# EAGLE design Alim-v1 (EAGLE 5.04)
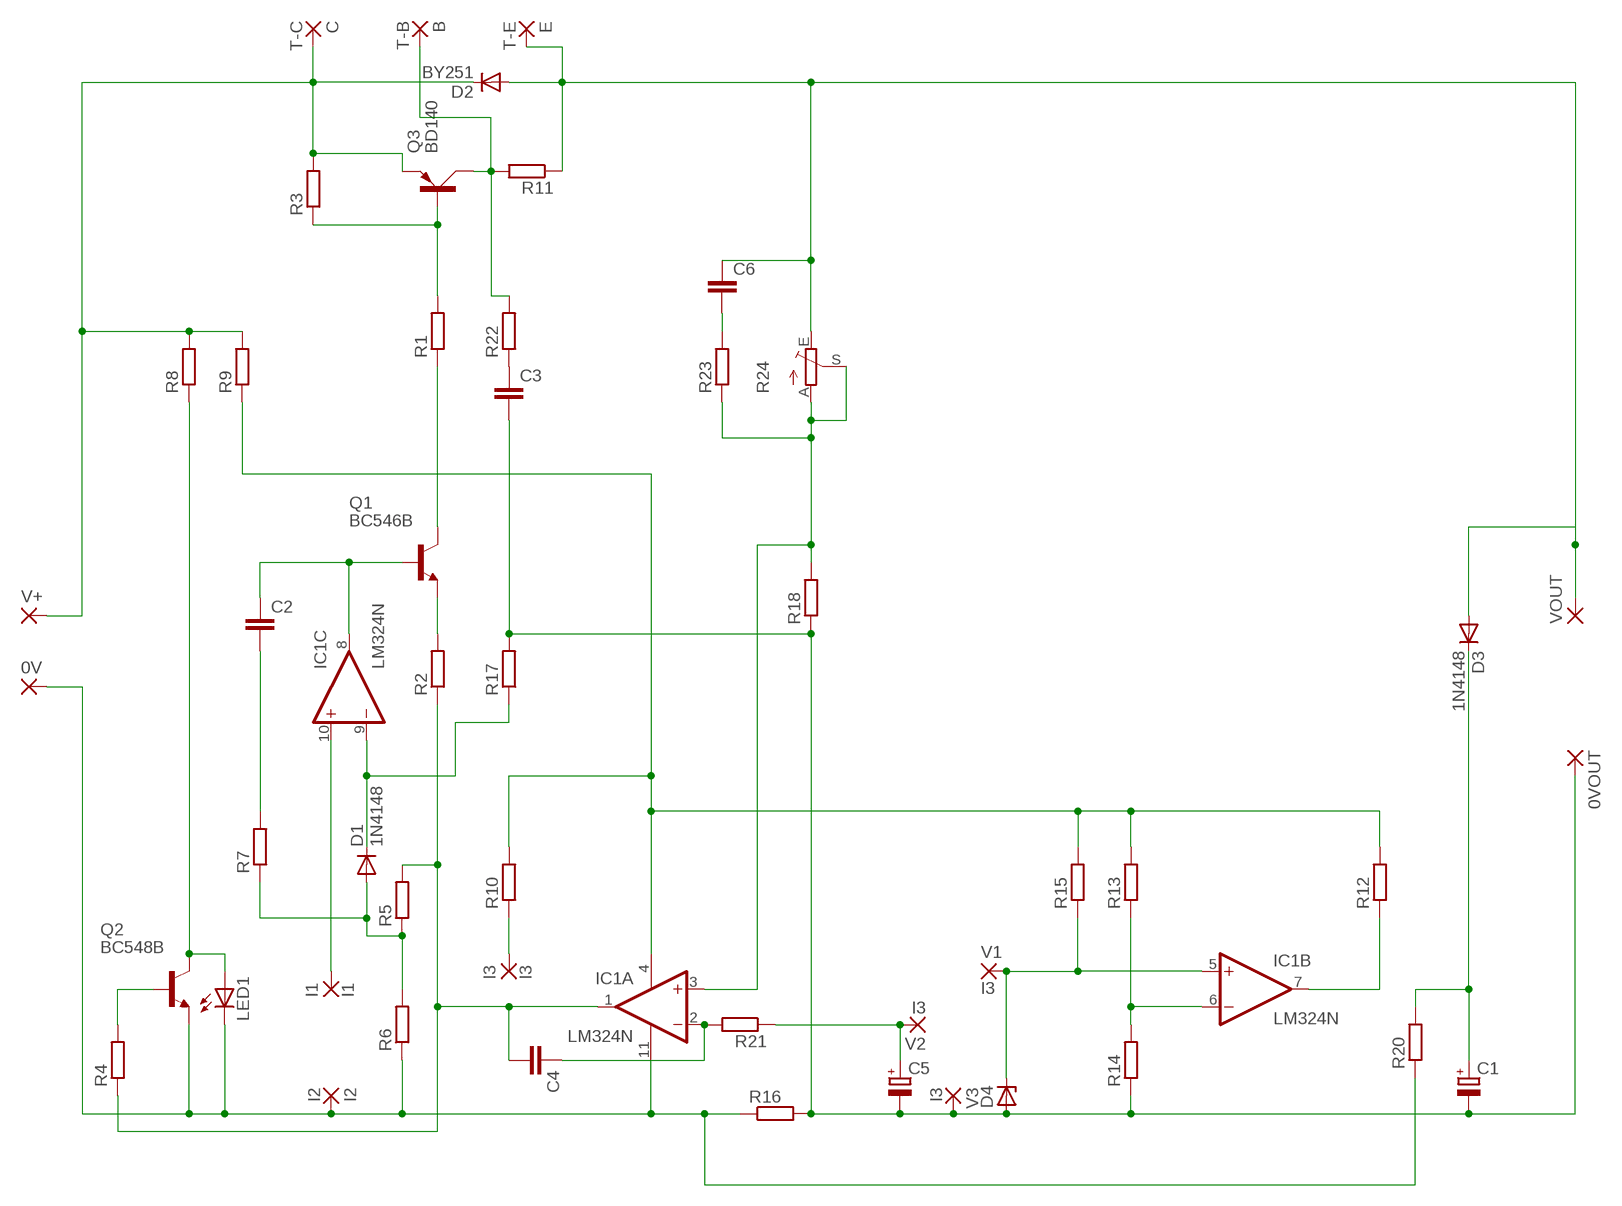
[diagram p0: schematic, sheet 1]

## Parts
0V  3,81/1,4  [3,81/1,4]
0VOUT  3,81/1,4  [3,81/1,4]
B  T-B  WIREPAD3,81/1,4  [3,81/1,4]
C  T-C  WIREPAD3,81/1,4  [3,81/1,4]
C1  CPOL-EUE2.5-5  [E2,5-5]
C2  C-EU025-025X050  [C025-025X050]
C3  C-EU025-025X050  [C025-025X050]
C4  C-EU025-025X050  [C025-025X050]
C5  CPOL-EUE2.5-5  [E2,5-5]
C6  C-EU025-025X050  [C025-025X050]
D1  1N4148  1N4148DO35-10  [DO35-10]
D2  BY251  [DO201-15]
D3  1N4148  1N4148DO35-10  [DO35-10]
D4  ZENER-DIODEDO41Z10  [DO41Z10]
E  T-E  WIREPAD3,81/1,4  [3,81/1,4]
I1  I1  WIREPAD1,6/0,9  [1,6/0,9]
I2  I2  WIREPAD1,6/0,9  [1,6/0,9]
I3  I3  WIREPAD1,6/0,9  [1,6/0,9]
IC1  LM324N  [DIL14]
LED1  LED5MM  [LED5MM]
Q1  BC546B  [TO92-EBC]
Q2  BC548B  [TO92-EBC]
Q3  BD140  [TO126AV]
R1  R-EU_0207/10  [0207/10]
R2  R-EU_0207/10  [0207/10]
R3  R-EU_0207/10  [0207/10]
R4  R-EU_0207/10  [0207/10]
R5  R-EU_0207/10  [0207/10]
R6  R-EU_0207/10  [0207/10]
R7  R-EU_0207/10  [0207/10]
R8  R-EU_0207/10  [0207/10]
R9  R-EU_0207/10  [0207/10]
R10  R-EU_0207/10  [0207/10]
R11  R-EU_0207/10  [0207/10]
R12  R-EU_0207/10  [0207/10]
R13  R-EU_0207/10  [0207/10]
R14  R-EU_0207/10  [0207/10]
R15  R-EU_0207/10  [0207/10]
R16  R-EU_0617/5V  [0617V]
R17  R-EU_0207/10  [0207/10]
R18  R-EU_0207/10  [0207/10]
R20  R-EU_0207/10  [0207/10]
R21  R-EU_0207/10  [0207/10]
R22  R-EU_0207/10  [0207/10]
R23  R-EU_0207/10  [0207/10]
R24  TRIM_EU-B64Y  [B64Y]
V1  I3  WIREPAD1,6/0,9  [1,6/0,9]
V2  I3  WIREPAD1,6/0,9  [1,6/0,9]
V3  I3  WIREPAD1,6/0,9  [1,6/0,9]
V+  3,81/1,4  [3,81/1,4]
VOUT  3,81/1,4  [3,81/1,4]

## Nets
N$1: Q3.B R1.2 R3.1
N$2: Q1.C R1.1
N$3: Q1.E R2.2
N$4: IC1.7(B:OUT) R12.1
N$5: Q2.B R4.2
N$6: C4.2 IC1.1(A:OUT) R2.1 R4.1 R5.2
N$7: D1.C IC1.9(C:-IN) R17.1
N$8: 0V.1(P) I2.1(P) IC1.11(P:V-) LED1.K(C) Q2.E R6.1 R16.1 R20.1
N$9: D1.A R5.1 R6.2 R7.1
N$10: LED1.A Q2.C R8.1
N$11: C.1(P) D2.C Q3.E R3.2 R8.2 R9.2 V+.1(P)
N$12: C2.1 IC1.8(C:OUT) Q1.B
N$13: I1.1(P) IC1.10(C:+IN)
N$14: I3.1(P) R10.1
N$15: IC1.4(P:V+) R9.1 R10.2 R12.2 R13.2 R15.2
N$16: 0VOUT.1(P) C1.- C3.2 C5.- D4.A R14.1 R16.2 R17.2 R18.1 V3.1(P)
N$17: B.1(P) Q3.C R11.2 R22.2
N$18: C6.1 D2.A D3.A E.1(P) R11.1 R24.E VOUT.1(P)
N$19: IC1.6(B:-IN) R13.1 R14.2
N$20: D4.C IC1.5(B:+IN) R15.1 V1.1(P)
N$21: IC1.3(A:+IN) R18.2 R23.1 R24.A R24.S
N$22: C4.1 IC1.2(A:-IN) R21.2
N$23: C2.2 R7.2
N$25: C1.+ D3.C R20.2
N$26: C3.1 R22.1
N$27: C5.+ R21.1 V2.1(P)
N$29: C6.2 R23.2
Unconnected: IC1.12(D:+IN) IC1.13(D:-IN) IC1.14(D:OUT)

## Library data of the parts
0V 0VOUT V+ VOUT = wirepad:3,81/1,4: THROUGH-HOLE PAD
B C E I1-I3 V1-V3 = wirepad:WIREPAD: Wire PAD connect wire on PCB
C1 C5 = rcl:CPOL-EU: POLARIZED CAPACITOR, European symbol
C2-C4 C6 = rcl:C-EU: CAPACITOR, European symbol
D1 D3 = diode:1N4148: DIODE
D2 = diode:BY251: DIODE
D4 = diode:ZENER-DIODE: Z-Diode
IC1 = linear:LM324: OP AMP
LED1 = led:LED: LED
Q1 = transistor-npn:BC546*: NPN Transistor
Q2 = transistor-npn:BC548*: NPN Transistor
Q3 = transistor-power:BD140: PNP TRANSISTOR
R1-R15 R17 R18 R20-R23 = resistor:R-EU_: RESISTOR, European symbol
R16 = rcl:R-EU_: RESISTOR, European symbol
R24 = pot:TRIM_EU-: POTENTIOMETER

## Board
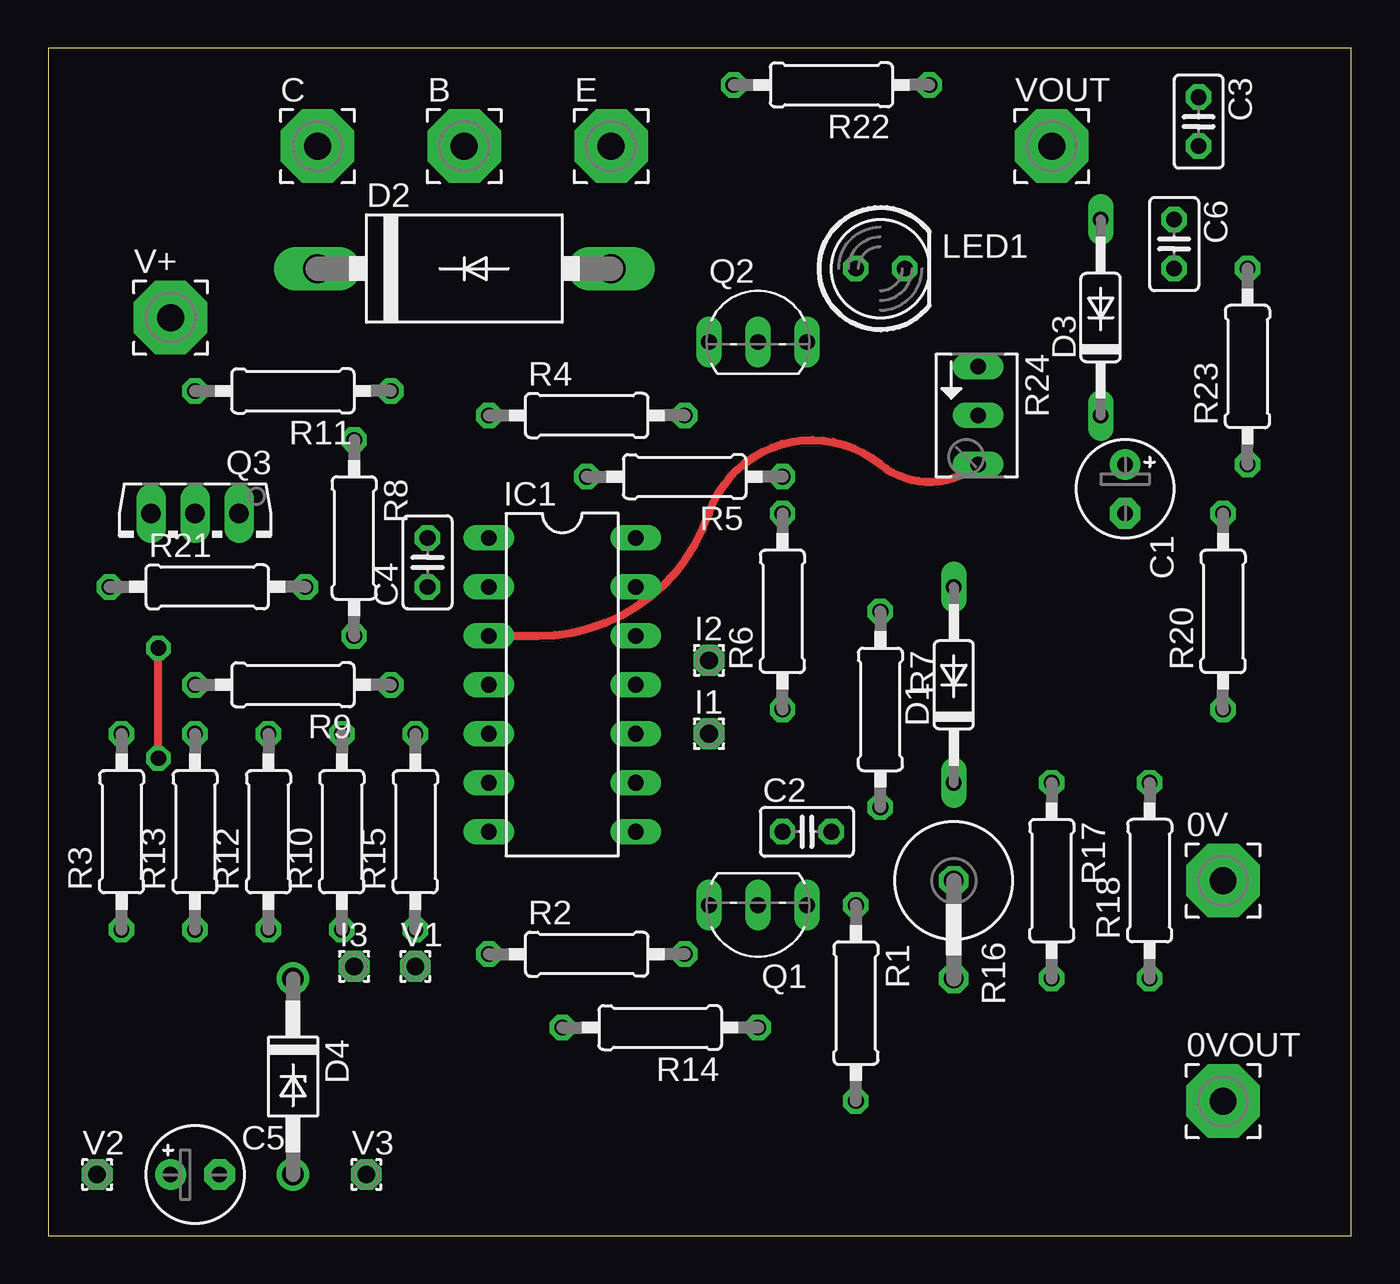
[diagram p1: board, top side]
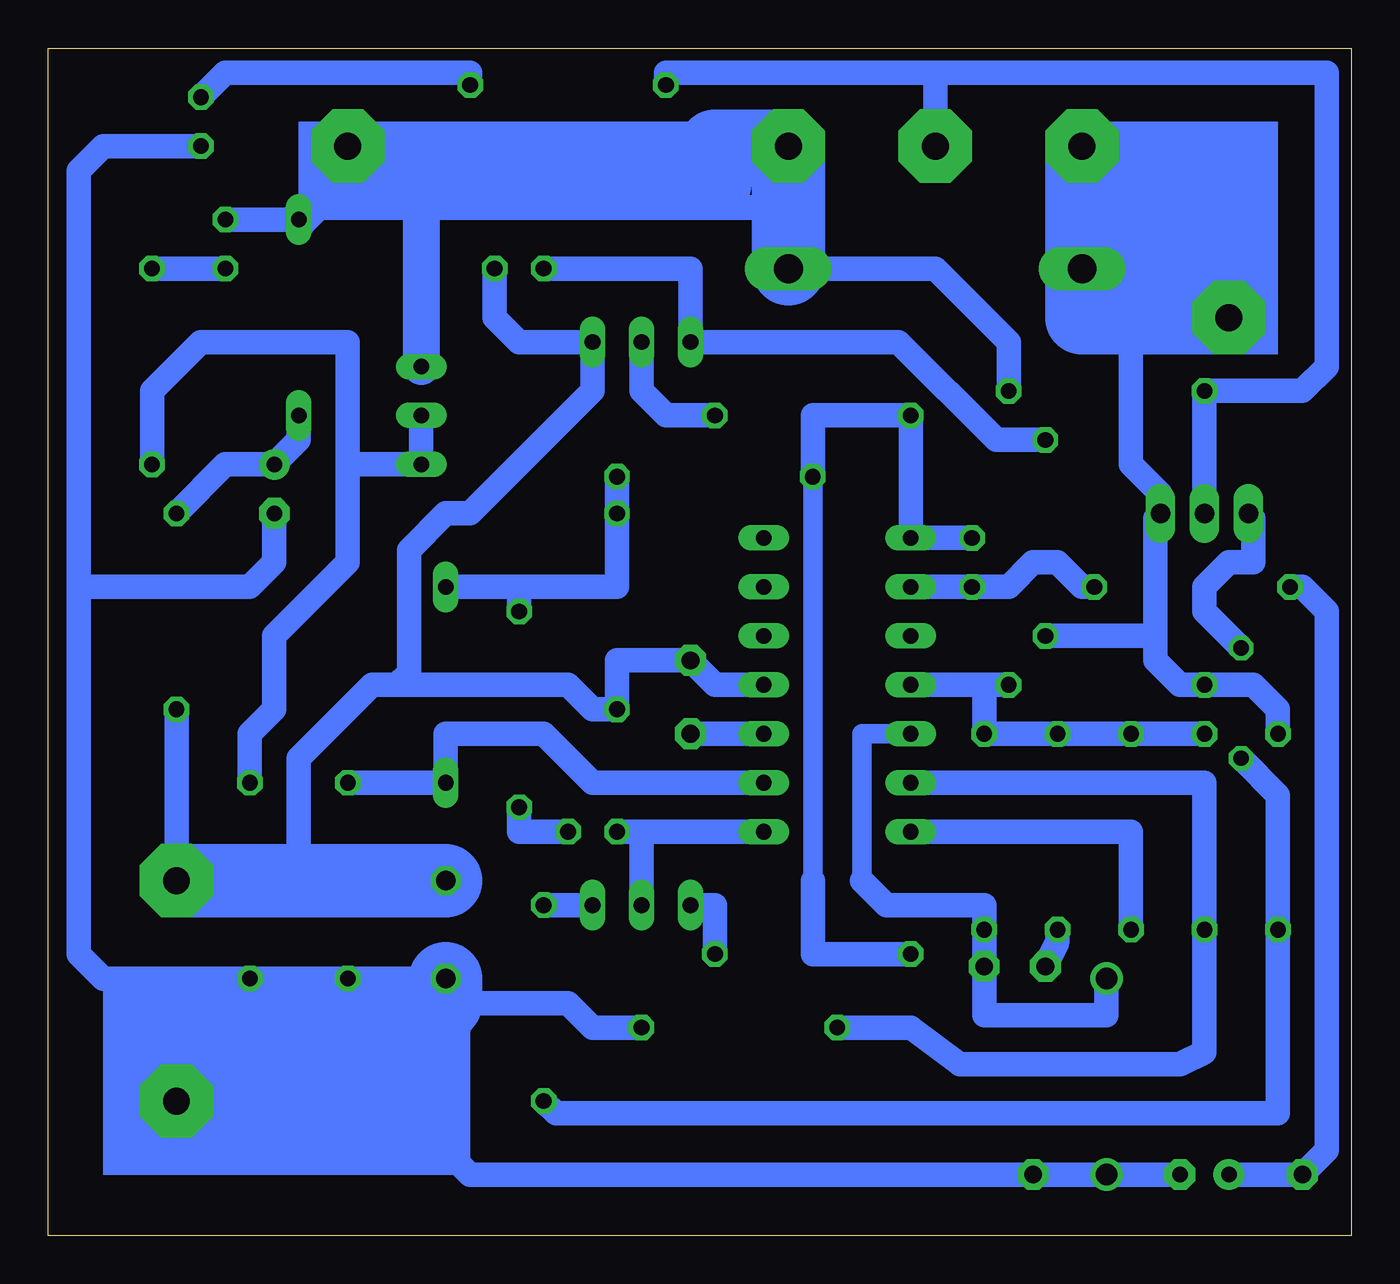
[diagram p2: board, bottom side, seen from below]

Size 67.61 x 61.59 mm. Coordinates in mm from the lower left corner, seen from the top.
Outline: 0,0 67.61,0 67.61,61.59 0,61.59 0,0
Copper layers (1*16): Top 0.035mm / dielectric 1.5mm / Bottom 0.035mm
Design rules "default": minimum track width 10mil, minimum drill 24mil, track to track 8mil, track to pad 8mil, pad to pad 8mil, via to via 8mil, smd to smd 8mil, copper to edge 40mil, drill to drill 8mil, minimum pad ring 10mil, minimum via ring 8mil, stop-mask expansion 4mil, vias tented up to drill 0mil, thermal gap 10mil

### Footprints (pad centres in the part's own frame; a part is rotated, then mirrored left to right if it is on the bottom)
3,81/1,4 = drill 1.397 pad 3.81 octagon: 1 0,0
E2,5-5 = drill 0.813 pad 1.6 round: + -1.27,0 | drill 0.813 pad 1.6 octagon: - 1.27,0
C025-025X050 = drill 0.813 octagon: 1 -1.27,0; 2 1.27,0
DO35-10 = drill 0.813 long: A 5.08,0; C -5.08,0
DO201-15 = drill 1.499 long: A 7.62,0; C -7.62,0
DO41Z10 = drill 1.118 round: A 5.08,0; C -5.08,0
1,6/0,9 = drill 0.914 pad 1.6 octagon: 1 0,0
DIL14 = drill 0.813 long: 1 -7.62,-3.81; 2 -5.08,-3.81; 3 -2.54,-3.81; 4 0,-3.81; 5 2.54,-3.81; 6 5.08,-3.81; 7 7.62,-3.81; 8 7.62,3.81; 9 5.08,3.81; 10 2.54,3.81; 11 0,3.81; 12 -2.54,3.81; 13 -5.08,3.81; 14 -7.62,3.81
LED5MM = drill 0.813 octagon: A -1.27,0; K 1.27,0
TO92-EBC = drill 0.813 long: B 0,-1.27; C -2.54,-1.27; E 2.54,-1.27
TO126AV = drill 1.016 long: B 2.286,-1.27; C 0,-1.27; E -2.286,-1.27
0207/10 = drill 0.813 octagon: 1 -5.08,0; 2 5.08,0
0617V = drill 1.016 octagon: 1 -2.54,0; 2 2.54,0
B64Y = drill 0.813 long: A 2.54,0; E -2.54,0; S 0,0

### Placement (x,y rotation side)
0V  60.96,18.41 0 top
0VOUT  60.96,6.98 0 top
B  21.59,56.52 0 top
C  13.97,56.52 0 top
C1  55.88,38.73 270 top
C2  39.37,20.95 0 top
C3  59.69,57.79 270 top
C4  19.68,34.93 90 top
C5  7.62,3.18 0 top
C6  58.42,51.43 270 top
D1  46.99,28.58 90 top
D2  21.59,50.16 0 top
D3  54.61,47.63 90 top
D4  12.7,8.26 270 top
E  29.21,56.52 0 top
I1  34.29,26.04 0 top
I2  34.29,29.84 0 top
I3  15.88,13.97 0 top
IC1  26.67,28.58 270 top
LED1  43.18,50.16 0 top
Q1  36.83,15.88 180 top
Q2  36.83,47.63 0 top
Q3  7.62,36.2 180 top
R1  41.91,12.07 270 top
R2  27.94,14.61 0 top
R3  3.81,20.95 90 top
R4  27.94,42.55 0 top
R5  33.02,39.37 180 top
R6  38.1,32.38 90 top
R7  43.18,27.3 270 top
R8  15.88,36.2 270 top
R9  12.7,28.58 180 top
R10  15.24,20.95 90 top
R11  12.7,43.81 180 top
R12  11.43,20.95 90 top
R13  7.62,20.95 90 top
R14  31.75,10.8 180 top
R15  19.05,20.95 90 top
R16  46.99,15.88 270 top
R17  52.07,18.41 270 top
R18  57.15,18.41 90 top
R20  60.96,32.38 90 top
R21  8.26,33.66 0 top
R22  40.64,59.69 180 top
R23  62.23,45.09 90 top
R24  48.26,42.55 270 top
V1  19.05,13.97 0 top
V2  2.54,3.18 0 top
V3  16.51,3.18 0 top
V+  6.35,47.63 0 top
VOUT  52.07,56.52 0 top

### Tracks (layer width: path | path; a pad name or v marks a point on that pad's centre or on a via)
N$1  (via drill 0.8 pad 1.27)
  Top 0.406: v5.71,24.77 v5.71,30.48
  Bottom 1.27: 3.81,14.61 3.81,6.35 41.28,6.35 R1.2 | 3.81,14.61 R3.1 | v5.71,30.48 7.62,32.38 7.62,33.66 6.35,34.93 5.08,34.93 5.08,37.21 Q3.B | 3.81,14.61 3.81,22.86 v5.71,24.77
N$2
  Bottom 1.27: Q1.C R1.1
N$3
  Bottom 1.27: R2.2 33.02,17.15 Q1.E
N$4
  Bottom 1.27: R12.1 11.43,20.95 IC1.7
N$5
  Bottom 1.27: R4.2 35.56,42.55 36.83,43.81 Q2.B
N$6
  Bottom 1.016: 27.94,18.41 R5.2
  Bottom 1.27: R2.1 27.94,14.61 27.94,18.41 | R5.2 27.94,42.55 R4.1 IC1.1 C4.2
N$7
  Bottom 1.27: IC1.9 39.37,23.49 41.91,26.04 46.99,26.04 D1.C R17.1
N$8
  Bottom 1.27: LED1.K 44.45,47.63 43.18,46.35 Q2.E 39.37,43.81 45.72,37.47 46.99,37.47 48.9,35.56 48.9,29.21 49.53,28.58 | 0V.1 R20.1 | IC1.11 33.02,28.58 I2.1 38.1,29.84 R6.1 39.37,27.3 40.64,28.58 49.53,28.58 | 49.53,28.58 50.8,28.58 54.61,24.77 54.61,18.41
  Bottom 3.81: R16.1 54.61,18.41 0V.1
N$9
  Bottom 1.27: R5.1 R6.2 38.1,33.66 43.18,33.66 | R7.1 43.18,33.66 | 43.18,33.66 D1.A
N$10
  Bottom 1.27: LED1.A 34.29,50.16 Q2.C 23.5,46.35 18.41,41.27 R8.1
N$11
  Bottom 1.27: 11.43,47.63 11.43,40.01 9.91,38.48 Q3.E 10.16,37.21 10.16,31.12 | R3.2 3.81,27.3 5.08,28.58 R9.2 8.89,28.58 10.16,29.84 10.16,31.12 | 10.16,31.12 R8.2
  Bottom 3.81: V+.1 11.43,47.63 13.97,47.63 D2.C C.1
N$12
  Bottom 1.27: IC1.8 36.83,20.95 | 36.83,20.95 C2.1 | 36.83,20.95 Q1.B
N$13
  Bottom 1.27: IC1.10 I1.1
N$14
  Bottom 1.27: R10.1 15.24,15.24 I3.1
N$15
  Bottom 1.27: R13.2 R12.2 R10.2 R15.2 19.05,28.58 | 19.05,28.58 IC1.4 | 19.05,28.58 R9.1
N$16
  Bottom 0.406: 66.04,33.66 66.04,36.2
  Bottom 1.27: C3.2 64.77,56.52 66.04,55.24 66.04,33.66 | C1.- 55.88,34.93 57.15,33.66 66.04,33.66 | 66.04,33.66 66.04,14.61 64.77,13.34 R18.1 R17.2 R16.2 | R14.1 39.37,10.8 40.64,12.07 46.99,12.07 46.99,4.45 45.72,3.18 V3.1 D4.A C5.-
  Bottom 3.81: R16.2 46.99,12.07 50.8,6.98 0VOUT.1
N$17
  Bottom 1.27: R22.2 35.56,60.32 21.59,60.32 | 21.59,60.32 1.27,60.32 1.27,45.09 2.54,43.81 R11.2 Q3.C | 21.59,60.32 B.1
N$18
  Bottom 1.27: D3.A C6.1 | D2.A 21.59,50.16 17.78,46.35 R11.1
  Bottom 1.93: 52.07,55.24 D3.A | 48.26,54.61 R24.E
  Bottom 3.81: VOUT.1 52.07,55.24 52.07,54.61 48.26,54.61 33.02,54.61 33.02,56.52 E.1 D2.A
N$19
  Bottom 1.27: R14.2 22.86,10.8 20.32,8.89 8.89,8.89 7.62,9.53 R13.1 7.62,23.49 IC1.6
N$20
  Bottom 1.016: 25.4,18.41 25.4,26.04 IC1.5
  Bottom 1.27: 25.4,18.41 24.13,17.15 19.05,17.15 R15.1 V1.1 19.05,11.43 12.7,11.43 D4.C
N$21
  Top 0.406: IC1.3 25.4,31.12 arc71 34.29,37.47 arc-110 43.18,40.01 arc78 R24.A
  Bottom 1.27: R23.1 62.23,43.81 59.69,46.35 52.07,46.35 52.07,40.01 | R18.2 57.15,26.04 55.88,27.3 55.88,31.12 52.07,34.93 52.07,40.01 | 52.07,40.01 R24.A R24.S
N$22
  Bottom 1.27: R21.2 13.97,33.66 15.24,34.93 16.51,34.93 17.78,33.66 C4.1 IC1.2
N$23
  Bottom 1.27: C2.2 43.18,20.95 R7.2
N$25
  Bottom 1.27: D3.C 54.61,41.27 C1.+ 58.42,40.01 R20.2
N$26
  Bottom 1.27: R22.1 45.72,60.32 58.42,60.32 C3.1
N$27
  Bottom 1.27: C5.+ V2.1 1.27,4.45 1.27,32.38 2.54,33.66 R21.1
N$29
  Bottom 1.27: C6.2 R23.2
(copper drawn outside any net)
  shapes: Bottom area x6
